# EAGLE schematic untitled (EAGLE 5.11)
PID: 896
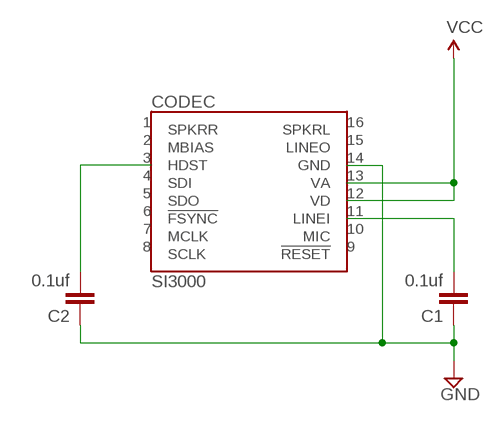
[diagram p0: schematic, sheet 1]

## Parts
C1  0.1uf  C-EUC0805  [C0805]
C2  0.1uf  C-EUC0805  [C0805]
CODEC  SI3000  [SO16]

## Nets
GND: C1.1 C2.1 CODEC.14(GND)
N$1: C1.2 CODEC.11(LINEI)
N$4: C2.2 CODEC.3(HDST)
VCC: CODEC.12(VD) CODEC.13(VA)
Unconnected: CODEC.1(SPKRR) CODEC.2(MBIAS) CODEC.4(SDI) CODEC.5(SDO) CODEC.6(!FSYNC) CODEC.7(MCLK) CODEC.8(SCLK) CODEC.9(!RESET) CODEC.10(MIC) CODEC.15(LINEO) CODEC.16(SPKRL)

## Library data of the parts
C1 C2 = resistor:C-EU: CAPACITOR, European symbol
CODEC = trl:SI3000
